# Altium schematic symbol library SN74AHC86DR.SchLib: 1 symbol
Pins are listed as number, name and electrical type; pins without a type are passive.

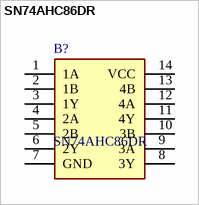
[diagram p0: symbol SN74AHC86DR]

## SN74AHC86DR
designator B?
Quadruple 2-Input Exclusive-OR Gates; Manufacturer_Name: Texas Instruments; Geometry.Height: 1.75mm
footprint SOIC127P600X175-14N
pins: 1 1A, 2 1B, 3 1Y, 4 2A, 5 2B, 6 2Y, 7 GND, 8 3Y, 9 3A, 10 3B, 11 4Y, 12 4A, 13 4B, 14 VCC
